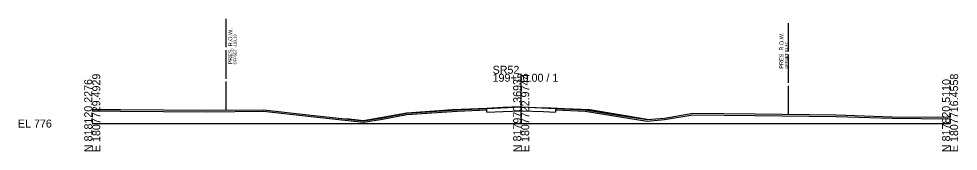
# Model space of a CAD drawing. Extents: x -50 to 1838305, y -27 to 820775.
# Drawn here: x -25.7 to 302.8, y 490.3 to 536.7 of the extents above; entities that cross this region are included whole.
import ezdxf

# ---------------------------------------------------------------- set-up
doc = ezdxf.new("R2010")
doc.units = 0
for name, color, linetype in [('DESIGN - EARTHWORK - Shapes', 7, 'Continuous'), ('DESIGN - SHEET - Light Grid', 7, 'Continuous'), ('DESIGN - TYPICAL - Finished Grade and Subgrade', 7, 'Continuous'), ('SURVEY - GROUND - Bottom of Topsoil Layer', 7, 'Continuous'), ('SURVEY - GROUND - Existing Pavement Layer', 7, 'Continuous'), ('SURVEY - GROUND - Top of Ground', 7, 'Continuous'), ('SURVEY - PROPERTY - ROW Lines', 7, 'Continuous'), ('SURVEY - PROPERTY - ROW Lines Text', 7, 'Continuous')]:
    doc.layers.add(name, color=color, linetype=linetype)

msp = doc.modelspace()

# ---------------------------------------------------------------- linework, layer by layer
at = {"layer": 'DESIGN - EARTHWORK - Shapes'}
for points in [[(109.98, 503.64), (94.82, 501), (101.53, 502.04)], [(109.98, 503.64), (94.82, 501), (101.53, 502.04)], [(109.98, 503.64), (94.82, 501), (101.53, 502.04)], [(126, 504.84), (109.98, 503.64), (120.53, 504.38), (127.64, 504.84), (138, 505.32)], [(138, 505.32), (126, 504.84), (109.98, 503.64), (120.53, 504.38), (127.64, 504.84)], [(126, 504.84), (109.98, 503.64), (120.53, 504.38), (127.64, 504.84), (138, 505.32)], [(138, 505.32), (150, 505.82), (143.6, 505.58)], [(138, 505.32), (150, 505.82), (143.6, 505.58)], [(138, 505.32), (150, 505.82), (143.6, 505.58)], [(174, 504.84), (194.12, 501.4), (184.67, 502.86), (172.41, 504.8), (157.88, 505.49), (162, 505.32)], [(174, 504.84), (194.12, 501.4), (184.67, 502.86), (172.41, 504.8), (157.88, 505.49), (162, 505.32)], [(162, 505.32), (172.41, 504.8), (184.67, 502.86), (194.12, 501.4), (174, 504.84)]]:
    msp.add_lwpolyline(points, close=True, dxfattribs=at)
at = {"layer": 'DESIGN - SHEET - Light Grid'}
for p, q in [((150, 500), (150, 517.45)), ((0, 500), (150, 500)), ((150, 500), (300, 500))]:
    msp.add_line(p, q, dxfattribs=at)
at = {"layer": 'DESIGN - TYPICAL - Finished Grade and Subgrade'}
for p, q in [((109.98, 503.64), (94.82, 501)), ((126, 504.84), (109.98, 503.64)), ((138, 505.32), (126, 504.84)), ((162, 505.32), (174, 504.84)), ((174, 504.84), (194.12, 501.4)), ((94.82, 501), (88.77, 501.65)), ((194.12, 501.4), (200.07, 501.94))]:
    msp.add_line(p, q, dxfattribs=at)
msp.add_lwpolyline([(138, 505.32), (150, 505.82), (162, 505.32)], dxfattribs=at)
at = {"layer": 'SURVEY - GROUND - Bottom of Topsoil Layer'}
for p, q in [((0, 504.43), (9.89, 504.39)), ((9.89, 504.39), (39.97, 504.17)), ((39.97, 504.17), (59.93, 504.31)), ((59.93, 504.31), (76.59, 502.46)), ((101.53, 501.54), (109.98, 503.14)), ((109.98, 503.14), (120.53, 503.88)), ((120.53, 503.88), (127.64, 504.34)), ((172.41, 504.3), (184.67, 502.36)), ((200.07, 501.44), (210.08, 503.1)), ((210.08, 503.1), (231.82, 502.88)), ((231.82, 502.88), (260.12, 502.52)), ((76.59, 502.46), (94.82, 500.5)), ((94.82, 500.5), (101.53, 501.54)), ((184.67, 502.36), (194.12, 500.9)), ((194.12, 500.9), (200.07, 501.44)), ((260.12, 502.52), (279.78, 501.85)), ((279.78, 501.85), (300, 501.71))]:
    msp.add_line(p, q, dxfattribs=at)
for points in [[(127.64, 504.34), (138, 504.82), (138, 505.32)], [(162, 505.29), (162, 504.79), (172.41, 504.3)]]:
    msp.add_lwpolyline(points, dxfattribs=at)
at = {"layer": 'SURVEY - GROUND - Existing Pavement Layer'}
for p, q in [((138, 504.01), (138, 505.32)), ((162, 505.29), (162, 503.98))]:
    msp.add_line(p, q, dxfattribs=at)
msp.add_lwpolyline([(138, 504.01), (143.66, 504.27), (150, 504.51), (157.83, 504.18), (162, 503.98)], dxfattribs=at)
at = {"layer": 'SURVEY - GROUND - Top of Ground'}
msp.add_lwpolyline([(0, 504.93), (9.89, 504.89), (39.97, 504.67), (59.93, 504.81), (76.59, 502.96), (94.82, 501), (101.53, 502.04), (109.98, 503.64), (120.53, 504.38), (127.64, 504.84), (143.6, 505.58), (150, 505.82), (157.88, 505.49), (172.41, 504.8), (184.67, 502.86), (194.12, 501.4), (200.07, 501.94), (210.08, 503.6), (231.82, 503.38), (260.12, 503.02), (279.78, 502.35), (300, 502.21)], dxfattribs=at)
at = {"layer": 'SURVEY - PROPERTY - ROW Lines'}
for p, q in [((46.81, 526.72), (46.81, 536.72)), ((243.47, 525.23), (243.47, 535.23)), ((46.81, 515.72), (46.81, 525.72)), ((243.47, 514.23), (243.47, 524.23)), ((46.81, 504.72), (46.81, 514.72)), ((243.47, 503.23), (243.47, 513.23))]:
    msp.add_line(p, q, dxfattribs=at)

# ---------------------------------------------------------------- texts
at = {"layer": 'DESIGN - SHEET - Light Grid'}
for s, p in [('SR52', (140, 517.45)), ('199+50.00 / 1', (140, 514.65)), ('EL 776', (-26, 498.6))]:
    msp.add_text(s, height=2.8, dxfattribs=at).set_placement(p)
for s, p in [('E 1807729.4929', (2.8, 490)), ('E 1807722.9744', (152.8, 490)), ('E 1807716.4558', (302.8, 490)), ('N 818120.2276', (0, 490)), ('N 817970.3693', (150, 490)), ('N 817820.5110', (300, 490))]:
    msp.add_text(s, height=2.8, rotation=90, dxfattribs=at).set_placement(p)
at = {"layer": 'SURVEY - PROPERTY - ROW Lines Text'}
for s, height, p in [('PRES. R.O.W.', 1.4, (48.96, 520.72)), ('OFFSET -103.19', 1, (50.46, 520.72)), ('PRES. R.O.W.', 1.4, (241.72, 519.23)), ('OFFSET 93.47', 1, (243.22, 519.23))]:
    msp.add_text(s, height=height, rotation=90, dxfattribs=at).set_placement(p)

doc.saveas('drawing.dxf')
